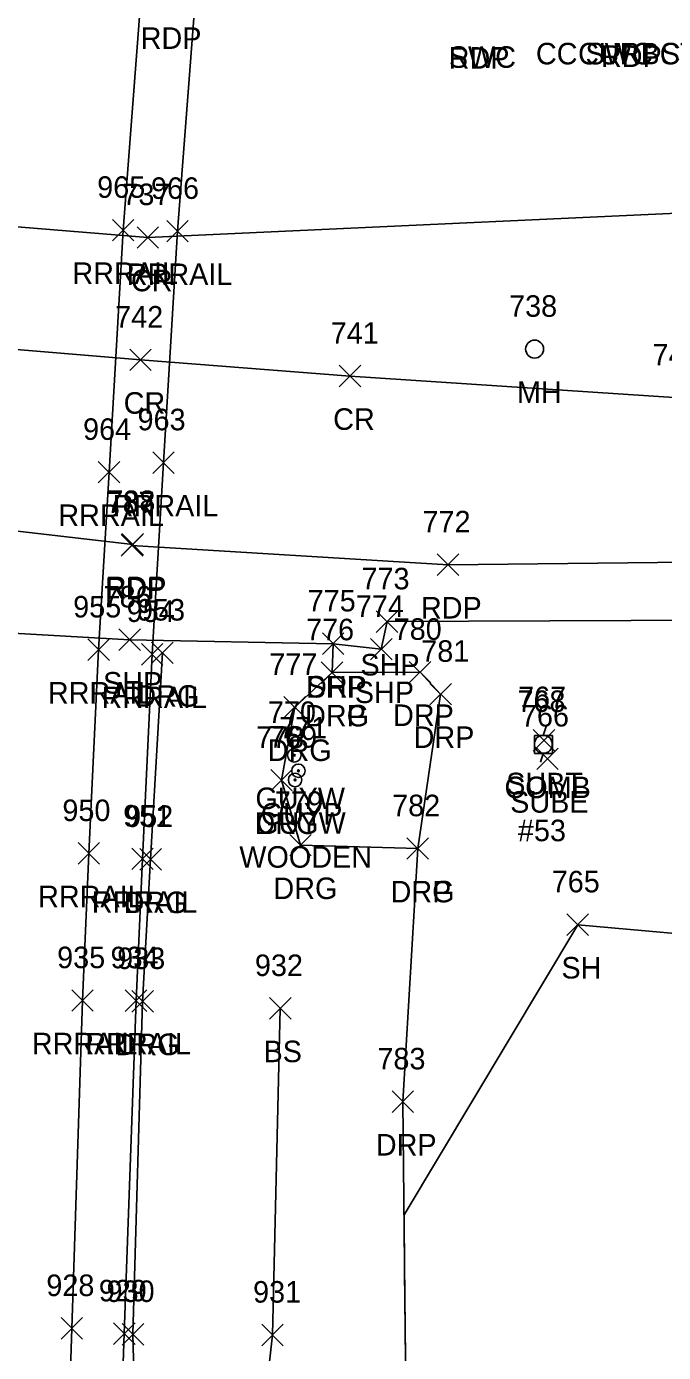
# Model space of a CAD drawing. Extents: x 1715662 to 1717487, y 887396 to 890004.
# Drawn here: x 1716460.7 to 1716519.9, y 888134.9 to 888258 of the extents above; entities that cross this region are included whole.
import ezdxf

# ---------------------------------------------------------------- set-up
doc = ezdxf.new("R2010")
doc.units = 0
for name, color, linetype in [('L_A', 7, 'Continuous'), ('L_I', 7, 'Continuous'), ('L_TIC', 7, 'Continuous'), ('LELB', 7, 'Continuous'), ('LSOGP', 7, 'Continuous'), ('P_A', 7, 'Continuous'), ('P_I', 7, 'Continuous'), ('P_TIC', 7, 'Continuous'), ('PET', 7, 'Continuous'), ('PRC', 7, 'Continuous'), ('PSP', 7, 'Continuous'), ('R_A', 7, 'Continuous'), ('R_I', 7, 'Continuous'), ('R_TIC', 7, 'Continuous'), ('RDG', 7, 'Continuous'), ('RDP', 7, 'Continuous'), ('RR', 7, 'Continuous'), ('U_A', 7, 'Continuous'), ('U_C', 7, 'Continuous'), ('U_I', 7, 'Continuous'), ('U_TIC', 7, 'Continuous'), ('UP', 7, 'Continuous'), ('UPGW', 7, 'Continuous'), ('UUMH', 7, 'Continuous')]:
    doc.layers.add(name, color=color, linetype=linetype)

msp = doc.modelspace()

# ---------------------------------------------------------------- linework, layer by layer
at = {"layer": 'L_TIC'}
for points in [[(1716510.9, 888173.6), (1716512.9, 888175.6)], [(1716512.9, 888173.6), (1716510.9, 888175.6)], [(1716483.28, 888165.83), (1716485.28, 888167.83)], [(1716485.28, 888165.83), (1716483.28, 888167.83)], [(1716482.55, 888135.5), (1716484.55, 888137.5)], [(1716484.55, 888135.5), (1716482.55, 888137.5)]]:
    msp.add_lwpolyline(points, dxfattribs=at)
at = {"layer": 'LELB'}
msp.add_lwpolyline([(1716473.94, 887913), (1716473.89, 887956.78), (1716474.68, 887987.26), (1716479.04, 888013.68), (1716476.32, 888035.41), (1716482.26, 888066.15), (1716480.22, 888093.78), (1716481.35, 888116.76), (1716483.55, 888136.5), (1716484.28, 888166.83)], dxfattribs=at)
at = {"layer": 'LSOGP'}
msp.add_lwpolyline([(1716495.94, 888131.85), (1716495.88, 888137.11), (1716495.83, 888142.38), (1716495.77, 888147.64), (1716511.9, 888174.6), (1716543.19, 888171.79), (1716574.85, 888176.12), (1716587.72, 888177.36), (1716591.77, 888181.6), (1716595.82, 888185.85), (1716600.22, 888185.86), (1716640.78, 888181.27), (1716639.39, 888169.56), (1716653.42, 888168.34), (1716667.9, 888172.89), (1716689.55, 888170.91), (1716693.25, 888191.71), (1716736.98, 888184.04)], dxfattribs=at)
at = {"layer": 'P_TIC'}
for points in [[(1716470.98, 888237.42), (1716472.98, 888239.42)], [(1716472.98, 888237.42), (1716470.98, 888239.42)], [(1716470.3, 888226.05), (1716472.3, 888228.05)], [(1716472.3, 888226.05), (1716470.3, 888228.05)], [(1716489.76, 888224.55), (1716491.76, 888226.55)], [(1716491.76, 888224.55), (1716489.76, 888226.55)], [(1716469.5, 888208.82), (1716471.5, 888210.82)], [(1716471.5, 888208.82), (1716469.5, 888210.82)], [(1716469.57, 888208.92), (1716471.57, 888210.92)], [(1716471.57, 888208.92), (1716469.57, 888210.92)], [(1716498.86, 888207.03), (1716500.86, 888209.03)], [(1716500.86, 888207.03), (1716498.86, 888209.03)], [(1716493.19, 888201.74), (1716495.19, 888203.74)], [(1716495.19, 888201.74), (1716493.19, 888203.74)], [(1716469.28, 888200.06), (1716471.28, 888202.06)], [(1716471.28, 888200.06), (1716469.28, 888202.06)], [(1716488.19, 888199.69), (1716490.19, 888201.69)], [(1716490.19, 888199.69), (1716488.19, 888201.69)], [(1716492.66, 888199.18), (1716494.66, 888201.18)], [(1716494.66, 888199.18), (1716492.66, 888201.18)]]:
    msp.add_lwpolyline(points, dxfattribs=at)
at = {"layer": 'PET'}
msp.add_lwpolyline([(1716662.11, 888208.93), (1716631.8, 888208.17), (1716598.77, 888208.88), (1716574.84, 888208.9), (1716547.13, 888208.53), (1716499.86, 888208.03), (1716470.5, 888209.82), (1716470.57, 888209.92), (1716434.17, 888214.11), (1716420.85, 888214.16)], dxfattribs=at)
at = {"layer": 'PRC'}
for points in [[(1716612.85, 888359.68), (1716612.17, 888345.49), (1716610.23, 888325.05), (1716599.91, 888295.77), (1716584.78, 888274.26), (1716560.31, 888253.42), (1716535.28, 888241.32), (1716471.98, 888238.42), (1716446.91, 888240.45), (1716423.44, 888242.23), (1716395.99, 888243.46), (1716360.07, 888243.38), (1716329.01, 888242.88), (1716285.79, 888240.52), (1716253.17, 888237.3), (1716220.47, 888232.04), (1716184.13, 888222.3), (1716155.75, 888211.83), (1716125.79, 888199.82), (1716096.66, 888186.57)], [(1716552.72, 888226.16), (1716521.3, 888223.53), (1716490.76, 888225.55), (1716471.3, 888227.05), (1716451.95, 888228.65), (1716428.34, 888230.29), (1716394.24, 888231.4), (1716360.6, 888231.76), (1716326.71, 888231.11), (1716290.95, 888229.37), (1716251.51, 888225.94), (1716222.8, 888221), (1716188.27, 888210.85), (1716159.49, 888199.86), (1716131.41, 888188.25), (1716103, 888175.83)]]:
    msp.add_lwpolyline(points, dxfattribs=at)
at = {"layer": 'PSP'}
msp.add_lwpolyline([(1716661.99, 888204.6), (1716631.89, 888203.79), (1716597.76, 888203.06), (1716574.64, 888203.27), (1716547.04, 888202.97), (1716494.19, 888202.74), (1716493.66, 888200.18), (1716489.19, 888200.69), (1716470.28, 888201.06), (1716436.75, 888202.98), (1716426.58, 888205.04), (1716425.59, 888209.88)], dxfattribs=at)
at = {"layer": 'R_TIC'}
for points in [[(1716468.68, 888238.1), (1716470.68, 888240.1)], [(1716470.68, 888238.1), (1716468.68, 888240.1)], [(1716473.73, 888238), (1716475.73, 888240)], [(1716475.73, 888238), (1716473.73, 888240)], [(1716472.43, 888216.51), (1716474.43, 888218.51)], [(1716474.43, 888216.51), (1716472.43, 888218.51)], [(1716467.37, 888215.62), (1716469.37, 888217.62)], [(1716469.37, 888215.62), (1716467.37, 888217.62)], [(1716466.4, 888199.13), (1716468.4, 888201.13)], [(1716468.4, 888199.13), (1716466.4, 888201.13)], [(1716488.19, 888199.69), (1716490.19, 888201.69)], [(1716490.19, 888199.69), (1716488.19, 888201.69)], [(1716471.38, 888198.71), (1716473.38, 888200.71)], [(1716473.38, 888198.71), (1716471.38, 888200.71)], [(1716472.33, 888198.84), (1716474.33, 888200.84)], [(1716474.33, 888198.84), (1716472.33, 888200.84)], [(1716488.09, 888197.01), (1716490.09, 888199.01)], [(1716490.09, 888197.01), (1716488.09, 888199.01)], [(1716488.09, 888197.01), (1716490.09, 888199.01)], [(1716490.09, 888197.01), (1716488.09, 888199.01)], [(1716496.26, 888197.05), (1716498.26, 888199.05)], [(1716498.26, 888197.05), (1716496.26, 888199.05)], [(1716498.17, 888195.01), (1716500.17, 888197.01)], [(1716500.17, 888195.01), (1716498.17, 888197.01)], [(1716484.62, 888193.8), (1716486.62, 888195.8)], [(1716486.62, 888193.8), (1716484.62, 888195.8)], [(1716483.39, 888187.02), (1716485.39, 888189.02)], [(1716485.39, 888187.02), (1716483.39, 888189.02)], [(1716485.15, 888180.98), (1716487.15, 888182.98)], [(1716487.15, 888180.98), (1716485.15, 888182.98)], [(1716496.04, 888180.67), (1716498.04, 888182.67)], [(1716498.04, 888180.67), (1716496.04, 888182.67)], [(1716496.04, 888180.67), (1716498.04, 888182.67)], [(1716498.04, 888180.67), (1716496.04, 888182.67)], [(1716465.49, 888180.22), (1716467.49, 888182.22)], [(1716467.49, 888180.22), (1716465.49, 888182.22)], [(1716470.48, 888179.71), (1716472.48, 888181.71)], [(1716472.48, 888179.71), (1716470.48, 888181.71)], [(1716471.23, 888179.67), (1716473.23, 888181.67)], [(1716473.23, 888179.67), (1716471.23, 888181.67)], [(1716464.91, 888166.56), (1716466.91, 888168.56)], [(1716466.91, 888166.56), (1716464.91, 888168.56)], [(1716469.88, 888166.55), (1716471.88, 888168.55)], [(1716471.88, 888166.55), (1716469.88, 888168.55)], [(1716470.49, 888166.48), (1716472.49, 888168.48)], [(1716472.49, 888166.48), (1716470.49, 888168.48)], [(1716494.66, 888157.16), (1716496.66, 888159.16)], [(1716496.66, 888157.16), (1716494.66, 888159.16)], [(1716463.91, 888136.11), (1716465.91, 888138.11)], [(1716465.91, 888136.11), (1716463.91, 888138.11)], [(1716468.79, 888135.62), (1716470.79, 888137.62)], [(1716470.79, 888135.62), (1716468.79, 888137.62)], [(1716469.59, 888135.56), (1716471.59, 888137.56)], [(1716471.59, 888135.56), (1716469.59, 888137.56)]]:
    msp.add_lwpolyline(points, dxfattribs=at)
at = {"layer": 'RDG'}
for points in [[(1716494.67, 888064.73), (1716482.26, 888066.15), (1716470.67, 888066.83), (1716471.5, 888094.68), (1716471.11, 888116.79), (1716470.59, 888136.56), (1716471.49, 888167.48), (1716472.23, 888180.67), (1716473.33, 888199.84)], [(1716489.09, 888198.01), (1716485.62, 888194.8), (1716484.39, 888188.02), (1716486.15, 888181.98), (1716497.04, 888181.67)]]:
    msp.add_lwpolyline(points, dxfattribs=at)
at = {"layer": 'RDP'}
msp.add_lwpolyline([(1716489.19, 888200.69), (1716489.09, 888198.01), (1716497.26, 888198.05), (1716499.17, 888196.01), (1716497.04, 888181.67), (1716495.66, 888158.16), (1716496.1, 888116.07), (1716495.98, 888097.59), (1716494.67, 888064.73)], dxfattribs=at)
at = {"layer": 'RR'}
for points in [[(1716461.02, 887983.96), (1716461.28, 888014.83), (1716461.93, 888036.88), (1716462.81, 888066.25), (1716463.2, 888072.92), (1716463.73, 888094.44), (1716464.22, 888116.34), (1716464.91, 888137.11), (1716465.91, 888167.56), (1716466.49, 888181.22), (1716467.4, 888200.13), (1716468.37, 888216.62), (1716469.68, 888239.1), (1716472.2, 888271.9), (1716474, 888290.95), (1716476.82, 888316.13), (1716479.36, 888334.44), (1716483, 888361.94), (1716487.31, 888387.93), (1716492.21, 888417.1)], [(1716461.97, 887885.39), (1716462.83, 887910.17), (1716464.45, 887957.38), (1716465.44, 887984.3), (1716466.28, 888014.51), (1716466.76, 888036.13), (1716467.79, 888066.64), (1716468.47, 888094.51), (1716469.09, 888116.58), (1716469.79, 888136.62), (1716470.88, 888167.55), (1716471.48, 888180.71), (1716472.38, 888199.71), (1716473.43, 888217.51), (1716474.73, 888239), (1716477.21, 888271.31), (1716478.99, 888290.56), (1716481.77, 888315.22), (1716484.18, 888333.14), (1716487.83, 888360.82), (1716492.09, 888386.99), (1716497, 888416.35)]]:
    msp.add_lwpolyline(points, dxfattribs=at)
at = {"layer": 'U_TIC'}
for points in [[(1716507.77, 888190.71), (1716509.77, 888192.71)], [(1716509.77, 888190.71), (1716507.77, 888192.71)], [(1716508.1, 888189), (1716510.1, 888191)], [(1716510.1, 888189), (1716508.1, 888191)]]:
    msp.add_lwpolyline(points, dxfattribs=at)
at = {"layer": 'UP'}
for p, q in [((1716508.96, 888193.01), (1716508.71, 888192.18)), ((1716507.88, 888190.51), (1716507.88, 888192.18)), ((1716507.88, 888192.18), (1716509.55, 888192.18)), ((1716508.71, 888191.35), (1716508.71, 888191.35)), ((1716509.55, 888192.18), (1716509.55, 888190.51)), ((1716509.55, 888190.51), (1716507.88, 888190.51)), ((1716508.46, 888189.68), (1716508.71, 888190.51))]:
    msp.add_line(p, q, dxfattribs=at)
msp.add_circle((1716508.71, 888191.35), 0.833, dxfattribs=at)
at = {"layer": 'UPGW'}
for centre, radius in [((1716485.58, 888190.33), 0.625), ((1716485.58, 888190.33), 0.0833), ((1716485.65, 888188.04), 0.625), ((1716485.96, 888188.89), 0.625), ((1716485.96, 888188.89), 0.0833), ((1716485.65, 888188.04), 0.0833)]:
    msp.add_circle(centre, radius, dxfattribs=at)
at = {"layer": 'UUMH'}
for p, q in [((1716507.9, 888228.05), (1716507.9, 888228.05)), ((1716508.73, 888228.05), (1716508.73, 888228.05))]:
    msp.add_line(p, q, dxfattribs=at)
msp.add_circle((1716507.9, 888228.05), 0.833, dxfattribs=at)

# ---------------------------------------------------------------- texts
at = {"layer": 'L_A'}
for s, p in [('SH', (1716510.39, 888169.6)), ('BS', (1716482.72, 888161.83))]:
    msp.add_text(s, height=2, dxfattribs=at).set_placement(p)
at = {"layer": 'L_I'}
for s, p in [('765', (1716509.49, 888177.6)), ('932', (1716481.92, 888169.83)), ('931', (1716481.75, 888139.5))]:
    msp.add_text(s, height=2, dxfattribs=at).set_placement(p)
at = {"layer": 'P_A'}
for s, p in [('RDP', (1716471.31, 888255.93)), ('RDP', (1716499.92, 888254.09)), ('RDP', (1716514.06, 888254.25)), ('CR', (1716470.41, 888233.42)), ('CR', (1716469.73, 888222.05)), ('CR', (1716489.19, 888220.55)), ('RDP', (1716467.99, 888204.82)), ('RDP', (1716468.06, 888204.92)), ('RDP', (1716497.34, 888203.03)), ('SHP', (1716491.72, 888197.74)), ('SHP', (1716467.82, 888196.06)), ('SHP', (1716486.72, 888195.69)), ('SHP', (1716491.2, 888195.18))]:
    msp.add_text(s, height=2, dxfattribs=at).set_placement(p)
at = {"layer": 'P_I'}
for s, p in [('737', (1716469.61, 888241.42)), ('742', (1716468.94, 888230.05)), ('741', (1716488.96, 888228.55)), ('740', (1716518.85, 888226.53)), ('787', (1716468.14, 888212.82)), ('788', (1716468.21, 888212.92)), ('772', (1716497.49, 888211.03)), ('773', (1716491.82, 888205.74)), ('786', (1716467.87, 888204.06)), ('775', (1716486.82, 888203.69)), ('774', (1716491.3, 888203.18))]:
    msp.add_text(s, height=2, dxfattribs=at).set_placement(p)
at = {"layer": 'R_A'}
for s, p in [('CC SWC ST', (1716508.02, 888254.49)), ('CURBC', (1716511.94, 888254.49)), ('SWC', (1716499.93, 888254.17)), ('RRRAIL', (1716464.97, 888234.1)), ('RRRAIL', (1716470.02, 888234)), ('RRRAIL', (1716468.72, 888212.51)), ('RRRAIL', (1716463.66, 888211.62)), ('DRP', (1716486.67, 888195.69)), ('RRRAIL', (1716462.69, 888195.13)), ('RRRAIL', (1716467.67, 888194.71)), ('DRG', (1716470.82, 888194.84)), ('DRG', (1716486.58, 888193.01)), ('DRP', (1716486.58, 888193.01)), ('DRP', (1716494.75, 888193.05)), ('DRP', (1716496.66, 888191.01)), ('DRG', (1716483.11, 888189.8)), ('DRG', (1716481.88, 888183.02)), ('DRG', (1716483.64, 888176.98)), ('RRRAIL', (1716461.78, 888176.22)), ('RRRAIL', (1716466.77, 888175.71)), ('DRG', (1716469.72, 888175.67)), ('DRG', (1716494.52, 888176.67)), ('DRP', (1716494.52, 888176.67)), ('RRRAIL', (1716461.2, 888162.56)), ('RRRAIL', (1716466.17, 888162.55)), ('DRG', (1716468.98, 888162.48)), ('DRP', (1716493.15, 888153.16))]:
    msp.add_text(s, height=2, dxfattribs=at).set_placement(p)
at = {"layer": 'R_I'}
for s, p in [('965', (1716467.27, 888242.1)), ('966', (1716472.27, 888242)), ('963', (1716471.02, 888220.51)), ('964', (1716465.96, 888219.62)), ('955', (1716465.04, 888203.13)), ('954', (1716470.01, 888202.71)), ('953', (1716470.97, 888202.84)), ('775', (1716486.82, 888203.69)), ('776', (1716486.67, 888201.01)), ('776', (1716486.67, 888201.01)), ('780', (1716494.81, 888201.05)), ('781', (1716497.37, 888199.01)), ('777', (1716483.26, 888197.8)), ('778', (1716482.03, 888191.02)), ('950', (1716464.04, 888184.22)), ('779', (1716483.78, 888184.98)), ('782', (1716494.67, 888184.67)), ('782', (1716494.67, 888184.67)), ('951', (1716469.68, 888183.71)), ('952', (1716469.87, 888183.67)), ('935', (1716463.55, 888170.56)), ('934', (1716468.51, 888170.55)), ('933', (1716469.13, 888170.48)), ('783', (1716493.3, 888161.16)), ('928', (1716462.55, 888140.11)), ('929', (1716467.42, 888139.62)), ('930', (1716468.14, 888139.56))]:
    msp.add_text(s, height=2, dxfattribs=at).set_placement(p)
at = {"layer": 'U_A'}
for s, p in [('MH', (1716506.26, 888223.05)), ('SUBT', (1716505.26, 888186.71)), ('COMB', (1716505.1, 888186.35)), ('GUYW', (1716481.97, 888185.33)), ('SUBE', (1716505.63, 888185)), ('GUYW', (1716482.04, 888183.04)), ('GUYP', (1716482.47, 888183.89))]:
    msp.add_text(s, height=2, dxfattribs=at).set_placement(p)
at = {"layer": 'U_C'}
for s, p in [('#53', (1716506.35, 888182.35)), ('WOODEN', (1716480.47, 888179.89))]:
    msp.add_text(s, height=2, dxfattribs=at).set_placement(p)
at = {"layer": 'U_I'}
for s, p in [('738', (1716505.53, 888231.05)), ('768', (1716506.3, 888194.35)), ('767', (1716506.36, 888194.71)), ('770', (1716483.13, 888193.33)), ('766', (1716506.63, 888193)), ('771', (1716484.17, 888191.89)), ('769', (1716483.23, 888191.04))]:
    msp.add_text(s, height=2, dxfattribs=at).set_placement(p)

doc.saveas('drawing.dxf')
